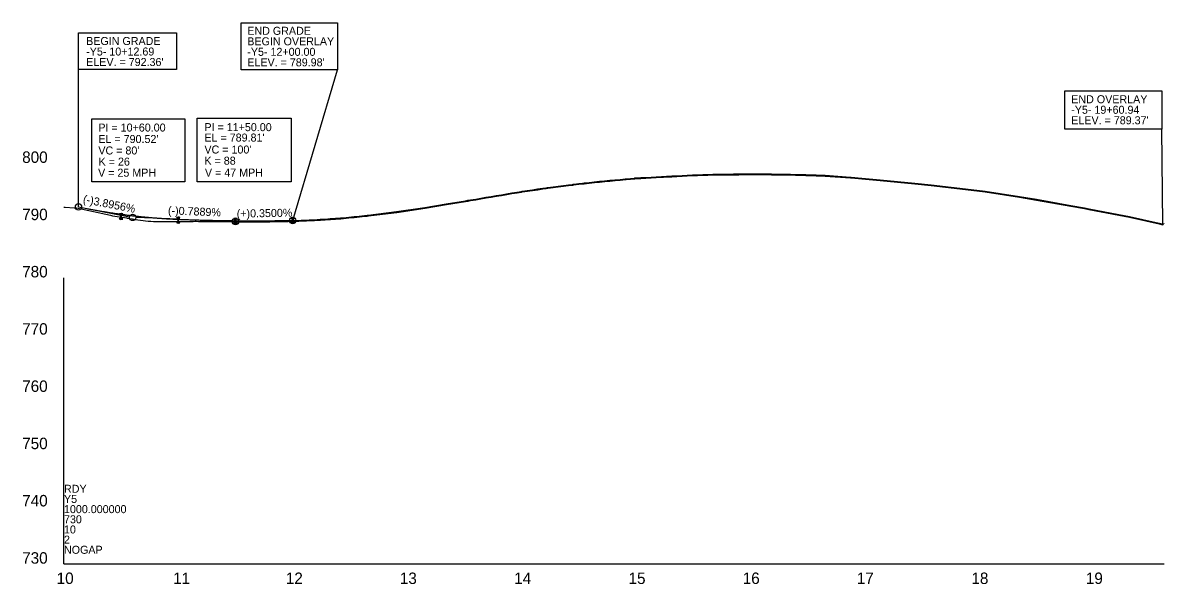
# Model space of a CAD drawing. Extents: x 579185 to 595036, y -53221 to -44640.
# Drawn here: x 584898 to 585896, y -49553 to -49063 of the extents above; entities that cross this region are included whole.
import ezdxf

# ---------------------------------------------------------------- set-up
doc = ezdxf.new("R2010")
doc.units = 0
for name, color, linetype in [('Exist Profile Cell', 7, 'Continuous'), ('Exist Vertical Profile Ground Line', 7, 'Continuous'), ('Exist Vertical Profile Horizontal Axis Label Major', 7, 'Continuous'), ('Exist Vertical Profile Vertical Axis Label', 7, 'Continuous'), ('Old_Level_2', 7, 'Continuous'), ('Prop Grid Mask', 7, 'Continuous'), ('Prop Vertical Profile Curve Label', 7, 'Continuous'), ('Prop Vertical Profile Grade', 7, 'Continuous'), ('Prop Vertical Profile Grade Label', 7, 'Continuous'), ('Prop VPI Label', 7, 'Continuous')]:
    doc.layers.add(name, color=color, linetype=linetype)

msp = doc.modelspace()

# ---------------------------------------------------------------- linework, layer by layer
at = {"layer": 'Exist Profile Cell'}
for q in [(584933.58, -49285.12), (585895.57, -49535.12), (584933.58, -49535.12)]:
    msp.add_line((584933.58, -49535.12), q, dxfattribs=at)
at = {"layer": 'Exist Vertical Profile Ground Line'}
for points in [[(584933.58, -49223.51), (584933.68, -49223.5), (584934.7, -49223.56), (584942.59, -49223.99), (584944.41, -49224.09), (584974.39, -49230.64), (584976.1, -49231.02), (584984.22, -49232.33), (584986.53, -49232.71), (584988.11, -49232.96), (584988.83, -49233.08), (584991.14, -49233.46), (584993.45, -49233.83), (584995.76, -49234.21), (584998.06, -49234.59), (585000.37, -49234.95), (585002.68, -49235.18), (585004.99, -49235.42), (585007.29, -49235.65), (585009.6, -49235.89), (585011.91, -49236.12), (585012.46, -49236.14), (585014.21, -49236.14), (585016.52, -49236.15), (585018.83, -49236.16), (585021.14, -49236.16), (585023.44, -49236.17), (585025.75, -49236.18), (585028.06, -49236.18), (585030.47, -49236.19), (585031.77, -49236.17), (585032.67, -49236.15), (585034.98, -49236.12), (585037.29, -49236.08), (585039.6, -49236.04), (585041.9, -49236), (585044.21, -49235.97), (585046.52, -49235.93), (585048.41, -49235.9), (585049.06, -49235.9), (585051.13, -49235.92), (585053.44, -49235.95), (585055.75, -49235.97), (585058.05, -49236), (585060.36, -49236.02), (585062.67, -49236.05), (585064.98, -49236.07), (585067.28, -49236.1), (585069.59, -49236.12), (585071.9, -49236.15), (585073.42, -49236.16), (585074.48, -49236.17), (585076.51, -49236.18), (585078.82, -49236.2), (585081.13, -49236.22), (585083.43, -49236.23), (585085.74, -49236.25), (585088.05, -49236.27), (585090.36, -49236.29), (585092.66, -49236.3), (585094.97, -49236.32), (585097.28, -49236.34), (585098.61, -49236.35), (585099.6, -49236.35), (585101.89, -49236.33), (585104.2, -49236.31), (585106.51, -49236.28), (585108.82, -49236.26), (585111.12, -49236.24), (585113.43, -49236.21), (585115.74, -49236.19), (585118.04, -49236.16), (585120.35, -49236.14), (585122.66, -49236.11), (585125.19, -49236.08), (585127.27, -49236.02), (585129.58, -49235.95), (585131.42, -49235.9), (585131.89, -49235.88), (585134.2, -49235.82), (585136.5, -49235.75), (585138.21, -49235.7), (585138.81, -49235.68), (585141.12, -49235.59), (585143.43, -49235.5), (585145.73, -49235.4), (585148.04, -49235.31), (585150.35, -49235.22), (585151.29, -49235.18), (585152.65, -49235.09), (585154.96, -49234.94), (585157.27, -49234.79), (585157.84, -49234.75), (585159.58, -49234.65), (585161.88, -49234.5), (585164.19, -49234.36), (585166.5, -49234.21), (585168.81, -49234.06), (585171.11, -49233.91), (585173.42, -49233.76), (585175.18, -49233.64), (585175.62, -49233.61), (585178.04, -49233.37), (585180.34, -49233.14), (585182.65, -49232.91), (585184.96, -49232.68), (585187.26, -49232.45), (585189.57, -49232.21), (585191.88, -49231.98), (585194.19, -49231.74), (585196.49, -49231.51), (585198.8, -49231.27), (585199.75, -49231.17), (585224.56, -49228.08), (585249.3, -49224.42), (585267.97, -49221.33), (585284.65, -49218.56), (585286.91, -49218.18), (585289.16, -49217.81), (585293.66, -49217.05), (585298.17, -49216.29), (585302.68, -49215.53), (585307.19, -49214.77), (585310.09, -49214.28), (585311.7, -49214.01), (585316.21, -49213.26), (585320.72, -49212.5), (585325.23, -49211.75), (585329.74, -49211), (585333.5, -49210.37), (585334.25, -49210.26), (585338.75, -49209.6), (585343.26, -49208.93), (585347.77, -49208.27), (585352.28, -49207.61), (585355.1, -49207.19), (585356.11, -49207.04), (585356.79, -49206.96), (585361.3, -49206.39), (585365.81, -49205.82), (585370.32, -49205.25), (585374.83, -49204.69), (585378.42, -49204.23), (585378.84, -49204.18), (585379.33, -49204.12), (585383.84, -49203.58), (585387.04, -49203.19), (585388.35, -49203.03), (585392.86, -49202.49), (585395.23, -49202.21), (585397.37, -49202.01), (585401.88, -49201.58), (585406.39, -49201.15), (585410.9, -49200.73), (585415.41, -49200.3), (585419.91, -49199.88), (585424.42, -49199.45), (585425.22, -49199.37), (585428.93, -49199.03), (585432.39, -49198.7), (585432.73, -49198.67), (585433.44, -49198.63), (585437.95, -49198.39), (585442.46, -49198.14), (585446.97, -49197.9), (585451.48, -49197.66), (585455.99, -49197.41), (585457.76, -49197.32), (585460.5, -49197.17), (585465, -49196.93), (585469.51, -49196.69), (585474.02, -49196.45), (585478.53, -49196.21), (585483.04, -49195.98), (585487.55, -49195.84), (585492.06, -49195.71), (585496.57, -49195.57), (585501.08, -49195.44), (585505.69, -49195.31), (585510.09, -49195.27), (585514.6, -49195.23), (585517.44, -49195.21), (585519.11, -49195.2), (585523.62, -49195.17), (585528.13, -49195.14), (585532.64, -49195.15), (585537.15, -49195.15), (585541.66, -49195.15), (585546.17, -49195.16), (585550.67, -49195.16), (585551.68, -49195.16), (585552.32, -49195.17), (585555.18, -49195.22), (585559.69, -49195.29), (585564.2, -49195.37), (585568.71, -49195.44), (585573.22, -49195.51), (585575.86, -49195.55), (585576.46, -49195.57), (585577.73, -49195.61), (585582.24, -49195.77), (585586.75, -49195.92), (585591.25, -49196.08), (585594.64, -49196.19), (585595.76, -49196.23), (585599.04, -49196.36), (585621.2, -49197.92), (585621.75, -49197.96), (585634.36, -49199.12), (585647.31, -49200.32), (585677.44, -49203.2), (585691.86, -49204.58), (585721.81, -49208.16), (585739.06, -49210.21), (585769.02, -49214.95), (585783.85, -49217.3), (585813.83, -49222.63), (585825.87, -49224.76), (585829.79, -49225.51), (585855.86, -49230.48), (585865.19, -49232.26), (585891.12, -49238.03), (585894.51, -49238.92), (585895.21, -49237.82), (585895.57, -49238.12)], [(585178.04, -49233.37), (585180.34, -49233.14), (585182.65, -49232.91), (585184.96, -49232.68), (585187.26, -49232.45), (585189.57, -49232.21), (585191.88, -49231.98), (585194.19, -49231.74), (585196.49, -49231.51), (585198.8, -49231.27)]]:
    msp.add_lwpolyline(points, dxfattribs=at)
at = {"layer": 'Old_Level_2'}
for p, q in [((584983.58, -49231.6), (584982.13, -49229.1)), ((584982.13, -49229.1), (584985.02, -49229.1)), ((584982.61, -49229.93), (584984.54, -49229.93)), ((584983.58, -49231.6), (584985.02, -49229.1)), ((584982.13, -49234.1), (584983.58, -49231.6)), ((584982.13, -49234.1), (584985.02, -49234.1)), ((584982.61, -49233.27), (584984.54, -49233.27)), ((584983.1, -49230.77), (584984.06, -49230.77)), ((584983.1, -49232.44), (584984.06, -49232.44)), ((584985.02, -49234.1), (584983.58, -49231.6)), ((585033.58, -49234.86), (585032.13, -49232.36)), ((585032.13, -49232.36), (585035.02, -49232.36)), ((585032.13, -49237.36), (585033.58, -49234.86)), ((585032.13, -49237.36), (585035.02, -49237.36)), ((585032.61, -49233.19), (585034.54, -49233.19)), ((585032.61, -49236.53), (585034.54, -49236.53)), ((585033.1, -49234.03), (585034.06, -49234.03)), ((585033.1, -49235.7), (585034.06, -49235.7)), ((585033.58, -49234.86), (585035.02, -49232.36)), ((585035.02, -49237.36), (585033.58, -49234.86)), ((585083.58, -49235.56), (585082.13, -49233.06)), ((585082.13, -49233.06), (585085.02, -49233.06)), ((585082.13, -49238.06), (585083.58, -49235.56)), ((585082.13, -49238.06), (585085.02, -49238.06)), ((585082.61, -49233.89), (585084.54, -49233.89)), ((585082.61, -49237.22), (585084.54, -49237.22)), ((585083.1, -49234.72), (585084.06, -49234.72)), ((585083.1, -49236.39), (585084.06, -49236.39)), ((585083.58, -49235.56), (585085.02, -49233.06)), ((585085.02, -49238.06), (585083.58, -49235.56)), ((585133.58, -49235.11), (585132.13, -49232.61)), ((585132.13, -49232.61), (585135.02, -49232.61)), ((585132.13, -49237.61), (585133.58, -49235.11)), ((585132.13, -49237.61), (585135.02, -49237.61)), ((585132.61, -49233.44), (585134.54, -49233.44)), ((585132.61, -49236.78), (585134.54, -49236.78)), ((585133.1, -49234.28), (585134.06, -49234.28)), ((585133.1, -49235.95), (585134.06, -49235.95)), ((585133.58, -49235.11), (585135.02, -49232.61)), ((585135.02, -49237.61), (585133.58, -49235.11))]:
    msp.add_line(p, q, dxfattribs=at)
at = {"layer": 'Prop Grid Mask'}
for points in [[(585088.42, -49062.58), (585172.7, -49062.58), (585172.7, -49103.64), (585088.42, -49103.64)], [(584946.4, -49071.4), (585031.84, -49071.4), (585031.84, -49103.37), (584946.4, -49103.37)], [(585808.59, -49121.89), (585893.6, -49121.89), (585893.6, -49155.5), (585808.59, -49155.5)], [(584958.01, -49146.52), (585039.15, -49146.52), (585039.15, -49201.41), (584958.01, -49201.41)], [(585050.06, -49145.76), (585132.19, -49145.76), (585132.19, -49201.3), (585050.06, -49201.3)]]:
    msp.add_lwpolyline(points, close=True, dxfattribs=at)
at = {"layer": 'Prop Vertical Profile Curve Label'}
for p, q in [((584946.27, -49223.31), (584946.4, -49103.37)), ((585133.58, -49235.2), (585172.7, -49103.64)), ((585894.52, -49238.28), (585893.6, -49155.5))]:
    msp.add_line(p, q, dxfattribs=at)
at = {"layer": 'Prop Vertical Profile Grade'}
msp.add_line((584946.27, -49223.31), (584953.58, -49224.74), dxfattribs=at)
msp.add_lwpolyline([(585133.58, -49235.21), (585134.18, -49235.19), (585136.49, -49235.13), (585138.18, -49235.08), (585138.79, -49235.06), (585141.09, -49234.96), (585143.4, -49234.87), (585145.71, -49234.78), (585148.02, -49234.69), (585150.32, -49234.6), (585151.26, -49234.56), (585152.61, -49234.47), (585154.92, -49234.32), (585157.23, -49234.17), (585157.8, -49234.13), (585159.54, -49234.02), (585161.84, -49233.88), (585164.15, -49233.73), (585166.46, -49233.58), (585168.77, -49233.44), (585171.07, -49233.29), (585173.38, -49233.14), (585175.14, -49233.02), (585175.57, -49232.99), (585177.97, -49232.75), (585180.28, -49232.52), (585182.59, -49232.29), (585184.89, -49232.06), (585187.2, -49231.83), (585189.51, -49231.59), (585191.82, -49231.36), (585194.12, -49231.12), (585196.43, -49230.89), (585198.74, -49230.65), (585199.68, -49230.55), (585224.47, -49227.46), (585249.21, -49223.8), (585267.87, -49220.72), (585284.54, -49217.94), (585286.8, -49217.57), (585289.05, -49217.19), (585293.56, -49216.43), (585298.07, -49215.67), (585302.58, -49214.91), (585307.09, -49214.15), (585309.99, -49213.66), (585311.6, -49213.39), (585316.11, -49212.64), (585320.62, -49211.89), (585325.12, -49211.13), (585329.63, -49210.38), (585333.4, -49209.75), (585334.15, -49209.64), (585338.66, -49208.98), (585343.17, -49208.32), (585347.68, -49207.65), (585352.19, -49206.99), (585355.01, -49206.57), (585356.03, -49206.42), (585356.71, -49206.34), (585361.22, -49205.77), (585365.73, -49205.2), (585370.24, -49204.63), (585374.75, -49204.07), (585378.34, -49203.61), (585378.76, -49203.56), (585379.26, -49203.5), (585383.77, -49202.95), (585386.96, -49202.57), (585388.28, -49202.41), (585392.79, -49201.87), (585395.16, -49201.59), (585397.31, -49201.38), (585401.82, -49200.96), (585406.33, -49200.53), (585410.84, -49200.1), (585415.35, -49199.68), (585419.86, -49199.25), (585424.36, -49198.83), (585425.16, -49198.75), (585428.87, -49198.4), (585432.33, -49198.08), (585432.68, -49198.05), (585433.41, -49198.01), (585437.92, -49197.76), (585442.43, -49197.52), (585446.93, -49197.28), (585451.44, -49197.03), (585455.95, -49196.79), (585457.73, -49196.7), (585460.46, -49196.55), (585464.97, -49196.31), (585469.48, -49196.07), (585473.99, -49195.83), (585478.5, -49195.59), (585483.02, -49195.36), (585487.53, -49195.22), (585492.04, -49195.08), (585496.55, -49194.95), (585501.06, -49194.81), (585505.68, -49194.68), (585510.09, -49194.64), (585514.6, -49194.61), (585517.43, -49194.59), (585519.11, -49194.57), (585523.62, -49194.55), (585528.13, -49194.52), (585532.64, -49194.52), (585537.15, -49194.52), (585541.66, -49194.53), (585546.17, -49194.53), (585550.67, -49194.53), (585551.69, -49194.53), (585552.33, -49194.54), (585555.19, -49194.59), (585559.7, -49194.67), (585564.21, -49194.74), (585568.72, -49194.81), (585573.23, -49194.89), (585575.87, -49194.93), (585576.48, -49194.94), (585577.75, -49194.99), (585582.26, -49195.14), (585586.77, -49195.3), (585591.28, -49195.45), (585594.66, -49195.57), (585595.79, -49195.61), (585599.08, -49195.74), (585621.24, -49197.3), (585621.8, -49197.33), (585634.42, -49198.5), (585647.37, -49199.69), (585677.5, -49202.58), (585691.93, -49203.96), (585721.89, -49207.54), (585739.14, -49209.59), (585769.11, -49214.33), (585783.95, -49216.68), (585813.94, -49222.01), (585825.99, -49224.15), (585829.91, -49224.9), (585855.98, -49229.87), (585865.32, -49231.65), (585891.27, -49237.42), (585894.52, -49238.28)], dxfattribs=at)
for points in [[(584953.58, -49224.74), (584955.18, -49225.04), (584956.78, -49225.35), (584958.38, -49225.65), (584959.98, -49225.94), (584961.58, -49226.23), (584963.18, -49226.52), (584964.78, -49226.79), (584966.38, -49227.07), (584967.98, -49227.34), (584969.58, -49227.6), (584971.18, -49227.86), (584972.78, -49228.12), (584974.38, -49228.37), (584975.98, -49228.61), (584977.58, -49228.85), (584979.18, -49229.09), (584980.78, -49229.31), (584982.38, -49229.54), (584983.98, -49229.76), (584985.58, -49229.97), (584987.18, -49230.18), (584988.78, -49230.39), (584990.38, -49230.59), (584991.98, -49230.78), (584993.58, -49230.97), (584995.18, -49231.16), (584996.78, -49231.34), (584998.38, -49231.51), (584999.98, -49231.68), (585001.58, -49231.85), (585003.18, -49232.01), (585004.78, -49232.16), (585006.38, -49232.31), (585007.98, -49232.46), (585009.58, -49232.6), (585011.18, -49232.73), (585012.78, -49232.86), (585014.38, -49232.99), (585015.98, -49233.11), (585017.58, -49233.22), (585019.18, -49233.33), (585020.78, -49233.44), (585022.38, -49233.54), (585023.98, -49233.64), (585025.58, -49233.73), (585027.18, -49233.81), (585028.78, -49233.89), (585030.38, -49233.97), (585031.98, -49234.04), (585033.58, -49234.1)], [(585033.58, -49234.1), (585035.58, -49234.18), (585037.58, -49234.26), (585039.58, -49234.33), (585041.58, -49234.4), (585043.58, -49234.47), (585045.58, -49234.54), (585047.58, -49234.6), (585049.58, -49234.66), (585051.58, -49234.72), (585053.58, -49234.78), (585055.58, -49234.83), (585057.58, -49234.89), (585059.58, -49234.94), (585061.58, -49234.99), (585063.58, -49235.03), (585065.58, -49235.07), (585067.58, -49235.12), (585069.58, -49235.16), (585071.58, -49235.19), (585073.58, -49235.23), (585075.58, -49235.26), (585077.58, -49235.29), (585079.58, -49235.32), (585081.58, -49235.34), (585083.58, -49235.36), (585085.58, -49235.39), (585087.58, -49235.4), (585089.58, -49235.42), (585091.58, -49235.43), (585093.58, -49235.45), (585095.58, -49235.46), (585097.58, -49235.46), (585099.58, -49235.47), (585101.58, -49235.47), (585103.58, -49235.47), (585105.58, -49235.47), (585107.58, -49235.46), (585109.58, -49235.46), (585111.58, -49235.45), (585113.58, -49235.44), (585115.58, -49235.42), (585117.58, -49235.41), (585119.58, -49235.39), (585121.58, -49235.37), (585123.58, -49235.35), (585125.58, -49235.32), (585127.58, -49235.3), (585129.58, -49235.27), (585131.58, -49235.24), (585133.58, -49235.2)]]:
    msp.add_spline(points, degree=3, dxfattribs=at)
at = {"layer": 'Prop VPI Label'}
for p, q in [((584953.58, -49224.74), (584990.88, -49232)), ((585033.58, -49234.1), (584996.33, -49232.63)), ((585033.58, -49234.1), (585080.83, -49235.97)), ((585133.58, -49235.2), (585086.33, -49236.03))]:
    msp.add_line(p, q, dxfattribs=at)
for centre in [(584946.27, -49223.31), (584993.58, -49232.53), (585083.58, -49236.08), (585133.58, -49235.2)]:
    msp.add_circle(centre, 2.75, dxfattribs=at)

# ---------------------------------------------------------------- texts
at = {"layer": 'Exist Profile Cell'}
for s, p in [('RDY', (584933.58, -49473)), ('Y5', (584933.58, -49481.87)), ('1000.000000', (584933.58, -49490.75)), ('730', (584933.58, -49499.62)), ('10', (584933.58, -49508.49)), ('2', (584933.58, -49517.37)), ('NOGAP', (584933.58, -49526.24))]:
    msp.add_text(s, height=7, dxfattribs=at).set_placement(p)
at = {"layer": 'Exist Vertical Profile Horizontal Axis Label Major'}
for s, p in [('10', (584927.16, -49552.62)), ('11', (585029, -49552.62)), ('12', (585127.55, -49552.62)), ('13', (585227.22, -49552.62)), ('14', (585327.28, -49552.62)), ('15', (585427.21, -49552.62)), ('16', (585527.04, -49552.62)), ('17', (585626.78, -49552.62)), ('18', (585727.01, -49552.62)), ('19', (585827.09, -49552.62))]:
    msp.add_text(s, height=10, dxfattribs=at).set_placement(p)
at = {"layer": 'Exist Vertical Profile Vertical Axis Label'}
for s, p in [('800', (584897.01, -49184.87)), ('790', (584897.01, -49234.87)), ('780', (584897.01, -49284.87)), ('770', (584897.01, -49334.87)), ('760', (584897.01, -49384.87)), ('750', (584897.01, -49434.87)), ('740', (584897.01, -49484.87)), ('730', (584897.01, -49534.87))]:
    msp.add_text(s, height=10, dxfattribs=at).set_placement(p)
at = {"layer": 'Old_Level_2'}
for p in [(584983.35, -49228.94), (584983.15, -49235.11), (585033.15, -49238.37), (585033.35, -49232.2), (585083.15, -49239.06), (585083.35, -49232.9), (585133.15, -49238.62), (585133.35, -49232.45)]:
    msp.add_text('6"', height=0.8, dxfattribs=at).set_placement(p)
at = {"layer": 'Prop Vertical Profile Curve Label'}
for s, p in [("VC = 80'", (584963.63, -49177.53)), ("VC = 100'", (585056.38, -49176.71)), ('K = 26', (584963.86, -49187.28)), ('K = 88', (585056.38, -49186.43)), ('V = 25 MPH', (584963.4, -49196.94)), ('V = 47 MPH', (585056.82, -49196.87))]:
    msp.add_text(s, height=7, dxfattribs=at).set_placement(p)
at = {"layer": 'Prop Vertical Profile Grade Label'}
for s, rotation, p in [('(-)3.8956%', 348.97798, (584949.77, -49219.73)), ('(-)0.7889%', 357.74117, (585024.39, -49229.83)), ('(+)0.3500%', 1.00257, (585084.67, -49232.68))]:
    msp.add_text(s, height=7, rotation=rotation, dxfattribs=at).set_placement(p)
at = {"layer": 'Prop VPI Label'}
for s, p in [('END GRADE', (585093.86, -49073.03)), ('BEGIN GRADE', (584952.96, -49081.94)), ('BEGIN OVERLAY', (585093.86, -49082.21)), ('-Y5- 10+12.69', (584952.96, -49091.12)), ('-Y5- 12+00.00', (585093.86, -49091.38)), ("ELEV. = 792.36'", (584952.96, -49100.29)), ("ELEV. = 789.98'", (585093.86, -49100.56)), ('END OVERLAY', (585814.32, -49132.8)), ('-Y5- 19+60.94', (585814.32, -49141.98)), ('PI = 10+60.00', (584963.63, -49157.53)), ('PI = 11+50.00', (585056.38, -49157.17)), ("ELEV. = 789.37'", (585814.32, -49151.15)), ("EL = 790.52'", (584963.63, -49167.53)), ("EL = 789.81'", (585056.38, -49166.25))]:
    msp.add_text(s, height=7, dxfattribs=at).set_placement(p)

doc.saveas('drawing.dxf')
